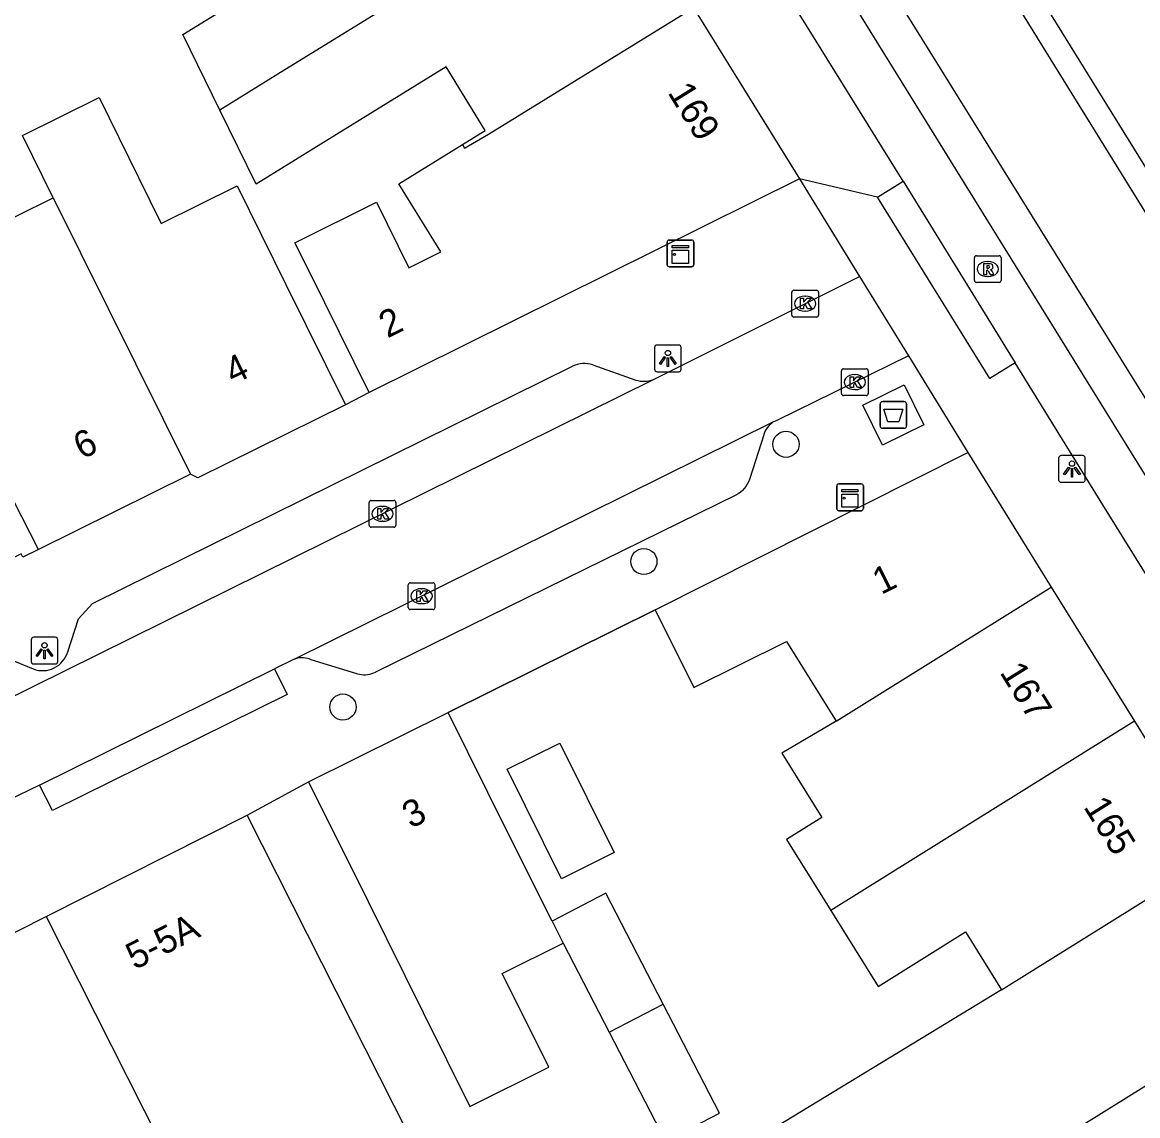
# Model space of a CAD drawing. Extents: x 159888 to 160757, y 384031 to 384746.
# Drawn here: x 160649.94 to 160691.65, y 384191.91 to 384232.8 of the extents above; entities that cross this region are included whole.
import ezdxf

# ---------------------------------------------------------------- set-up
doc = ezdxf.new("R2010")
doc.units = 0
for name, color, linetype in [('IMGEO_Afval_apart_plaats', 7, 'Continuous'), ('IMGEO_Boom', 7, 'Continuous'), ('IMGEO_Kast', 7, 'Continuous'), ('IMGEO_Kolk', 7, 'Continuous'), ('IMGEO_Lichtpunt', 7, 'Continuous'), ('IMGEO_Muur', 7, 'Continuous'), ('IMGEO_Pand', 7, 'Continuous'), ('IMGEO_Pand_nummerreeks', 7, 'Continuous'), ('IMGEO_Rijbaan_lokaal_gesloten', 7, 'Continuous'), ('IMGEO_Rijbaan_lokaal_open', 7, 'Continuous'), ('IMGEO_Rioolput', 7, 'Continuous'), ('IMGEO_Voetpad_gesloten', 7, 'Continuous'), ('IMGEO_Voetpad_open', 7, 'Continuous')]:
    doc.layers.add(name, color=color, linetype=linetype)

msp = doc.modelspace()

# ---------------------------------------------------------------- linework, layer by layer
at = {"layer": 'IMGEO_Afval_apart_plaats'}
for p, q in [((160682.013, 384217.714), (160682.013, 384218.514)), ((160682.013, 384218.514), (160682.013, 384217.714)), ((160682.113, 384218.614), (160682.903, 384218.614)), ((160682.903, 384218.614), (160682.113, 384218.614)), ((160683.003, 384218.514), (160683.003, 384217.714)), ((160683.003, 384217.714), (160683.003, 384218.514)), ((160682.903, 384217.614), (160682.113, 384217.614)), ((160682.113, 384217.614), (160682.903, 384217.614))]:
    msp.add_line(p, q, dxfattribs=at)
msp.add_lwpolyline([(160682.156, 384218.328), (160682.86, 384218.328), (160682.711, 384217.858), (160682.305, 384217.858), (160682.156, 384218.328)], dxfattribs=at)
for centre, start, end in [((160682.113, 384218.514), 90, 180), ((160682.113, 384218.514), 90, 180), ((160682.903, 384218.514), 0, 90), ((160682.903, 384218.514), 360, 90), ((160682.113, 384217.714), 180, 270), ((160682.113, 384217.714), 180, 270), ((160682.903, 384217.714), 270, 0), ((160682.903, 384217.714), 270, 0)]:
    msp.add_arc(centre, 0.1, start, end, dxfattribs=at)
at = {"layer": 'IMGEO_Boom'}
for centre in [(160678.495, 384217.017), (160673.18, 384212.633), (160661.928, 384207.19)]:
    msp.add_circle(centre, 0.489, dxfattribs=at)
at = {"layer": 'IMGEO_Kast'}
for p, q in [((160674.048, 384223.73), (160674.048, 384224.571)), ((160674.048, 384224.571), (160674.048, 384223.73)), ((160674.123, 384224.655), (160674.964, 384224.655)), ((160674.964, 384224.655), (160674.123, 384224.655)), ((160675.048, 384224.58), (160675.048, 384223.739)), ((160675.048, 384223.739), (160675.048, 384224.58)), ((160674.973, 384223.655), (160674.132, 384223.655)), ((160674.132, 384223.655), (160674.973, 384223.655)), ((160680.39, 384214.609), (160680.39, 384215.45)), ((160680.39, 384215.45), (160680.39, 384214.609)), ((160680.465, 384215.534), (160681.306, 384215.534)), ((160681.306, 384215.534), (160680.465, 384215.534)), ((160681.39, 384215.459), (160681.39, 384214.618)), ((160681.39, 384214.618), (160681.39, 384215.459)), ((160681.315, 384214.534), (160680.474, 384214.534)), ((160680.474, 384214.534), (160681.315, 384214.534))]:
    msp.add_line(p, q, dxfattribs=at)
for points in [[(160674.243, 384224.445), (160674.843, 384224.445), (160674.843, 384224.36), (160674.243, 384224.36), (160674.243, 384224.445)], [(160674.243, 384224.27), (160674.843, 384224.27), (160674.843, 384223.781), (160674.243, 384223.781), (160674.243, 384224.27)], [(160680.585, 384215.324), (160681.185, 384215.324), (160681.185, 384215.239), (160680.585, 384215.239), (160680.585, 384215.324)], [(160680.585, 384215.149), (160681.185, 384215.149), (160681.185, 384214.66), (160680.585, 384214.66), (160680.585, 384215.149)]]:
    msp.add_lwpolyline(points, dxfattribs=at)
for centre in [(160674.327, 384224.119), (160680.669, 384214.998)]:
    msp.add_circle(centre, 0.0377, dxfattribs=at)
for centre, start, end in [((160674.126, 384224.577), 92.4484, 184.2845), ((160674.126, 384224.577), 92.4484, 184.2845), ((160674.97, 384224.577), 2.4484, 94.2845), ((160674.97, 384224.577), 2.4484, 94.2845), ((160674.126, 384223.733), 182.4484, 274.2845), ((160674.126, 384223.733), 182.4484, 274.2845), ((160674.97, 384223.733), 272.4484, 4.2845), ((160674.97, 384223.733), 272.4484, 4.2845), ((160680.468, 384215.456), 92.4484, 184.2845), ((160680.468, 384215.456), 92.4484, 184.2845), ((160681.312, 384215.456), 2.4484, 94.2845), ((160681.312, 384215.456), 2.4484, 94.2845), ((160680.468, 384214.612), 182.4484, 274.2845), ((160680.468, 384214.612), 182.4484, 274.2845), ((160681.312, 384214.612), 272.4484, 4.2845), ((160681.312, 384214.612), 272.4484, 4.2845)]:
    msp.add_arc(centre, 0.0779, start, end, dxfattribs=at)
at = {"layer": 'IMGEO_Kolk'}
for p, q in [((160678.71, 384221.85), (160678.71, 384222.702)), ((160678.785, 384222.776), (160679.637, 384222.776)), ((160679.198, 384222.556), (160679.223, 384222.556)), ((160679.711, 384222.702), (160679.711, 384221.85)), ((160679.637, 384221.776), (160678.785, 384221.776)), ((160679.221, 384221.996), (160679.196, 384221.996)), ((160680.569, 384218.915), (160680.569, 384219.767)), ((160680.644, 384219.841), (160681.496, 384219.841)), ((160681.057, 384219.621), (160681.082, 384219.621)), ((160681.57, 384219.767), (160681.57, 384218.915)), ((160681.496, 384218.841), (160680.644, 384218.841)), ((160681.08, 384219.061), (160681.055, 384219.061)), ((160662.906, 384213.99), (160662.906, 384214.842)), ((160662.981, 384214.916), (160663.833, 384214.916)), ((160663.394, 384214.696), (160663.419, 384214.696)), ((160663.907, 384214.842), (160663.907, 384213.99)), ((160663.417, 384214.136), (160663.392, 384214.136)), ((160663.833, 384213.916), (160662.981, 384213.916)), ((160664.368, 384210.911), (160664.368, 384211.763)), ((160664.443, 384211.837), (160665.295, 384211.837)), ((160664.856, 384211.617), (160664.881, 384211.617)), ((160665.369, 384211.763), (160665.369, 384210.911)), ((160665.295, 384210.837), (160664.443, 384210.837)), ((160664.879, 384211.057), (160664.854, 384211.057))]:
    msp.add_line(p, q, dxfattribs=at)
for points in [[(160678.71, 384221.85), (160678.71, 384222.702)], [(160678.785, 384222.776), (160679.637, 384222.776)], [(160679.031, 384222.476), (160679.154, 384222.476), (160679.154, 384222.325), (160679.284, 384222.476), (160679.448, 384222.476), (160679.302, 384222.325), (160679.455, 384222.076), (160679.303, 384222.076), (160679.218, 384222.24), (160679.154, 384222.173), (160679.154, 384222.076), (160679.031, 384222.076), (160679.031, 384222.476)], [(160679.711, 384222.702), (160679.711, 384221.85)], [(160679.637, 384221.776), (160678.785, 384221.776)], [(160680.569, 384218.915), (160680.569, 384219.767)], [(160680.644, 384219.841), (160681.496, 384219.841)], [(160680.89, 384219.541), (160681.013, 384219.541), (160681.013, 384219.39), (160681.143, 384219.541), (160681.307, 384219.541), (160681.161, 384219.39), (160681.314, 384219.141), (160681.162, 384219.141), (160681.077, 384219.305), (160681.013, 384219.238), (160681.013, 384219.141), (160680.89, 384219.141), (160680.89, 384219.541)], [(160681.57, 384219.767), (160681.57, 384218.915)], [(160681.496, 384218.841), (160680.644, 384218.841)], [(160662.906, 384213.99), (160662.906, 384214.842)], [(160662.981, 384214.916), (160663.833, 384214.916)], [(160663.227, 384214.616), (160663.35, 384214.616), (160663.35, 384214.465), (160663.48, 384214.616), (160663.644, 384214.616), (160663.498, 384214.465), (160663.651, 384214.216), (160663.499, 384214.216), (160663.414, 384214.38), (160663.35, 384214.313), (160663.35, 384214.216), (160663.227, 384214.216), (160663.227, 384214.616)], [(160663.907, 384214.842), (160663.907, 384213.99)], [(160663.833, 384213.916), (160662.981, 384213.916)], [(160664.368, 384210.911), (160664.368, 384211.763)], [(160664.443, 384211.837), (160665.295, 384211.837)], [(160665.369, 384211.763), (160665.369, 384210.911)], [(160664.689, 384211.537), (160664.812, 384211.537), (160664.812, 384211.386), (160664.942, 384211.537), (160665.106, 384211.537), (160664.96, 384211.386), (160665.113, 384211.137), (160664.961, 384211.137), (160664.876, 384211.301), (160664.812, 384211.234), (160664.812, 384211.137), (160664.689, 384211.137), (160664.689, 384211.537)], [(160665.295, 384210.837), (160664.443, 384210.837)]]:
    msp.add_lwpolyline(points, dxfattribs=at)
for centre, start, end in [((160678.787, 384222.7), 91.552, 178.448), ((160678.787, 384222.7), 91.552, 178.448), ((160679.635, 384222.7), 1.552, 88.448), ((160679.635, 384222.7), 1.552, 88.448), ((160678.787, 384221.852), 181.552, 268.448), ((160678.787, 384221.852), 181.552, 268.448), ((160679.635, 384221.852), 271.552, 358.448), ((160679.635, 384221.852), 271.552, 358.448), ((160680.646, 384219.765), 91.552, 178.448), ((160680.646, 384219.765), 91.552, 178.448), ((160681.494, 384219.765), 1.552, 88.448), ((160681.494, 384219.765), 1.552, 88.448), ((160680.646, 384218.917), 181.552, 268.448), ((160680.646, 384218.917), 181.552, 268.448), ((160681.494, 384218.917), 271.552, 358.448), ((160681.494, 384218.917), 271.552, 358.448), ((160662.983, 384214.84), 91.552, 178.448), ((160662.983, 384214.84), 91.552, 178.448), ((160663.831, 384214.84), 1.552, 88.448), ((160663.831, 384214.84), 1.552, 88.448), ((160662.983, 384213.992), 181.552, 268.448), ((160662.983, 384213.992), 181.552, 268.448), ((160663.831, 384213.992), 271.552, 358.448), ((160663.831, 384213.992), 271.552, 358.448), ((160664.445, 384211.761), 91.552, 178.448), ((160664.445, 384211.761), 91.552, 178.448), ((160665.293, 384211.761), 1.552, 88.448), ((160665.293, 384211.761), 1.552, 88.448), ((160664.445, 384210.913), 181.552, 268.448), ((160664.445, 384210.913), 181.552, 268.448), ((160665.293, 384210.913), 271.552, 358.448), ((160665.293, 384210.913), 271.552, 358.448)]:
    msp.add_arc(centre, 0.0765, start, end, dxfattribs=at)
for centre, major_axis, ratio, start_param, end_param in [((160679.197, 384222.276), (-0.387, 0.002), 0.722429, 4.712389, 7.853982), ((160679.222, 384222.276), (-0.39, 0.002), 0.717154, 1.570796, 4.712389), ((160681.056, 384219.341), (-0.387, 0.002), 0.722429, 4.712389, 7.853982), ((160681.081, 384219.341), (-0.39, 0.002), 0.717154, 1.570796, 4.712389), ((160663.393, 384214.416), (-0.387, 0.002), 0.722429, 4.712389, 7.853982), ((160663.418, 384214.416), (-0.39, 0.002), 0.717154, 1.570796, 4.712389), ((160664.855, 384211.337), (-0.387, 0.002), 0.722429, 4.712389, 7.853982), ((160664.88, 384211.337), (-0.39, 0.002), 0.717154, 1.570796, 4.712389)]:
    msp.add_ellipse(centre, major_axis=major_axis, ratio=ratio, start_param=start_param, end_param=end_param, dxfattribs=at)
at = {"layer": 'IMGEO_Lichtpunt'}
for p, q in [((160673.579, 384220.632), (160673.579, 384219.825)), ((160673.579, 384220.632), (160673.579, 384219.825)), ((160674.481, 384220.727), (160673.673, 384220.727)), ((160674.481, 384220.727), (160673.673, 384220.727)), ((160674.575, 384219.825), (160674.575, 384220.632)), ((160674.575, 384219.825), (160674.575, 384220.632)), ((160673.673, 384219.731), (160674.481, 384219.731)), ((160673.673, 384219.731), (160674.481, 384219.731)), ((160688.69, 384216.498), (160688.69, 384215.691)), ((160688.69, 384216.498), (160688.69, 384215.691)), ((160689.592, 384216.593), (160688.784, 384216.593)), ((160689.592, 384216.593), (160688.784, 384216.593)), ((160689.686, 384215.691), (160689.686, 384216.498)), ((160689.686, 384215.691), (160689.686, 384216.498)), ((160688.784, 384215.597), (160689.592, 384215.597)), ((160688.784, 384215.597), (160689.592, 384215.597)), ((160650.269, 384209.705), (160650.269, 384208.898)), ((160650.269, 384209.705), (160650.269, 384208.898)), ((160651.171, 384209.8), (160650.363, 384209.8)), ((160651.171, 384209.8), (160650.363, 384209.8)), ((160651.265, 384208.898), (160651.265, 384209.705)), ((160651.265, 384208.898), (160651.265, 384209.705)), ((160650.363, 384208.804), (160651.171, 384208.804)), ((160650.363, 384208.804), (160651.171, 384208.804))]:
    msp.add_line(p, q, dxfattribs=at)
for points in [[(160673.953, 384220.296), (160673.992, 384220.268), (160673.804, 384220.006), (160673.766, 384220.033), (160673.953, 384220.296)], [(160674.055, 384220.248), (160674.102, 384220.248), (160674.102, 384219.926), (160674.055, 384219.926), (160674.055, 384220.248)], [(160674.165, 384220.268), (160674.203, 384220.295), (160674.39, 384220.033), (160674.351, 384220.005), (160674.165, 384220.268)], [(160689.064, 384216.162), (160689.103, 384216.134), (160688.915, 384215.872), (160688.877, 384215.899), (160689.064, 384216.162)], [(160689.166, 384216.114), (160689.213, 384216.114), (160689.213, 384215.792), (160689.166, 384215.792), (160689.166, 384216.114)], [(160689.276, 384216.134), (160689.314, 384216.161), (160689.501, 384215.899), (160689.462, 384215.871), (160689.276, 384216.134)], [(160650.643, 384209.369), (160650.682, 384209.341), (160650.494, 384209.079), (160650.456, 384209.106), (160650.643, 384209.369)], [(160650.745, 384209.321), (160650.792, 384209.321), (160650.792, 384208.999), (160650.745, 384208.999), (160650.745, 384209.321)], [(160650.855, 384209.341), (160650.893, 384209.368), (160651.08, 384209.106), (160651.041, 384209.078), (160650.855, 384209.341)]]:
    msp.add_lwpolyline(points, dxfattribs=at)
for centre in [(160674.078, 384220.43), (160689.189, 384216.296), (160650.768, 384209.503)]:
    msp.add_circle(centre, 0.0994, dxfattribs=at)
for centre, start, end in [((160673.673, 384220.632), 90, 180), ((160673.673, 384220.632), 90, 180), ((160674.481, 384220.632), 0, 90), ((160674.481, 384220.632), 0, 90), ((160673.673, 384219.825), 180, 270), ((160673.673, 384219.825), 180, 270), ((160674.481, 384219.825), 270, 0), ((160674.481, 384219.825), 270, 360), ((160688.784, 384216.498), 90, 180), ((160688.784, 384216.498), 90, 180), ((160689.592, 384216.498), 0, 90), ((160689.592, 384216.498), 0, 90), ((160688.784, 384215.691), 180, 270), ((160688.784, 384215.691), 180, 270), ((160689.592, 384215.691), 270, 0), ((160689.592, 384215.691), 270, 360), ((160650.363, 384209.705), 90, 180), ((160650.363, 384209.705), 90, 180), ((160651.171, 384209.705), 0, 90), ((160651.171, 384209.705), 0, 90), ((160650.363, 384208.898), 180, 270), ((160650.363, 384208.898), 180, 270), ((160651.171, 384208.898), 270, 0), ((160651.171, 384208.898), 270, 360)]:
    msp.add_arc(centre, 0.0946, start, end, dxfattribs=at)
at = {"layer": 'IMGEO_Muur'}
msp.add_lwpolyline([(160673.598, 384210.83), (160665.86, 384206.987)], dxfattribs=at)
at = {"layer": 'IMGEO_Pand'}
for points in [[(160657.328, 384229.515), (160655.945, 384232.335), (160657.853, 384233.512), (160662.545, 384236.406), (160660.934, 384239.017)], [(160671.847, 384238.47), (160659.494, 384230.851), (160657.328, 384229.515)], [(160666.399, 384228.221), (160666.475, 384228.095), (160667.372, 384228.613), (160675.03, 384233.336)], [(160675.03, 384233.336), (160678.996, 384226.937)], [(160666.399, 384228.221), (160667.25, 384228.746), (160665.782, 384231.126), (160661.104, 384228.241), (160658.685, 384226.749), (160657.328, 384229.515)], [(160651.091, 384226.236), (160649.946, 384228.562), (160652.809, 384229.978), (160654.283, 384226.998), (160655.136, 384225.274), (160657.971, 384226.676), (160659.79, 384222.989), (160662.02, 384218.494)], [(160662.908, 384218.955), (160660.686, 384223.434), (160660.129, 384224.555), (160663.179, 384226.068), (160664.394, 384223.618), (160665.582, 384224.207), (160664.014, 384226.75), (160666.399, 384228.221)], [(160678.996, 384226.937), (160662.908, 384218.955)], [(160645.281, 384223.362), (160648.366, 384224.888), (160651.091, 384226.236)], [(160651.091, 384226.236), (160656.229, 384215.896)], [(160650.541, 384213.08), (160645.281, 384223.362)], [(160662.02, 384218.494), (160656.495, 384215.761), (160656.229, 384215.896)], [(160673.598, 384210.83), (160685.288, 384216.712)], [(160685.288, 384216.712), (160688.415, 384211.673)], [(160656.229, 384215.896), (160650.541, 384213.08)], [(160650.541, 384213.08), (160649.956, 384212.791), (160649.889, 384212.925), (160648.732, 384212.352), (160648.556, 384211.832), (160644.57, 384209.86)], [(160680.37, 384206.667), (160688.415, 384211.673)], [(160688.415, 384211.673), (160691.525, 384206.661)], [(160673.598, 384210.83), (160675.044, 384207.922), (160678.514, 384209.648), (160680.37, 384206.667)], [(160660.644, 384204.395), (160665.86, 384206.987)], [(160669.751, 384199.187), (160668.085, 384202.51), (160665.86, 384206.987)], [(160680.37, 384206.667), (160678.336, 384205.463), (160679.83, 384203.065), (160678.511, 384202.244), (160680.165, 384199.587)], [(160691.525, 384206.661), (160680.165, 384199.587)], [(160691.525, 384206.661), (160694.635, 384201.648)], [(160670.096, 384200.773), (160668.064, 384204.862), (160670.042, 384205.845), (160672.074, 384201.756), (160670.096, 384200.773)], [(160660.644, 384204.395), (160662.869, 384199.918), (160664.932, 384195.766), (160666.678, 384192.252), (160669.631, 384193.719), (160667.885, 384197.233), (160670.163, 384198.364)], [(160650.827, 384199.354), (160658.343, 384203.154)], [(160660.564, 384181.252), (160667.614, 384184.816), (160660.599, 384198.692), (160658.343, 384203.154)], [(160686.554, 384196.619), (160694.635, 384201.648)], [(160673.903, 384196.08), (160671.756, 384200.226), (160669.751, 384199.187)], [(160680.165, 384199.587), (160681.936, 384196.743), (160685.208, 384198.78), (160686.554, 384196.619)], [(160645.288, 384196.144), (160646.908, 384196.934), (160646.735, 384197.286), (160650.827, 384199.354)], [(160650.827, 384199.354), (160655.718, 384189.681)], [(160669.751, 384199.187), (160670.163, 384198.364)], [(160670.163, 384198.364), (160671.887, 384195.032)], [(160686.554, 384196.619), (160674.878, 384189.514), (160677.899, 384184.55), (160682.168, 384187.071)], [(160697.746, 384196.634), (160686.466, 384189.61), (160682.168, 384187.071)], [(160671.887, 384195.032), (160673.903, 384196.08)], [(160671.887, 384195.032), (160673.994, 384190.964), (160676.011, 384192.009), (160673.903, 384196.08)]]:
    msp.add_lwpolyline(points, dxfattribs=at)
at = {"layer": 'IMGEO_Rijbaan_lokaal_gesloten'}
for points in [[(160632.074, 384323.722), (160677.924, 384250), (160717.593, 384185.942), (160721.789, 384179.196), (160722.103, 384178.75)], [(160721.392, 384178.231), (160720.54, 384179.603), (160716.199, 384186.525), (160676.893, 384250), (160631.369, 384323.299)], [(160716.812, 384178.507), (160712.066, 384186.351), (160658.156, 384273.096), (160628.254, 384321.427)], [(160725.705, 384157.813), (160717.699, 384173.243), (160713.185, 384181.538), (160666.822, 384256.425), (160627.201, 384320.153), (160626.898, 384320.642)]]:
    msp.add_lwpolyline(points, dxfattribs=at)
at = {"layer": 'IMGEO_Rijbaan_lokaal_open'}
for points in [[(160673.544, 384219.435), (160681.241, 384223.295)], [(160681.241, 384223.295), (160683.08, 384220.328)], [(160683.08, 384220.328), (160678.178, 384217.924), (160678.008, 384217.84)], [(160647.891, 384206.746), (160673.544, 384219.435)], [(160678.008, 384217.84), (160660.093, 384208.974)], [(160660.093, 384208.974), (160660.082, 384208.969), (160659.372, 384208.618)], [(160650.586, 384204.276), (160659.372, 384208.618)], [(160650.586, 384204.276), (160649.402, 384203.691)]]:
    msp.add_lwpolyline(points, dxfattribs=at)
at = {"layer": 'IMGEO_Rioolput'}
for p, q in [((160685.539, 384223.142), (160685.539, 384223.994)), ((160685.614, 384224.068), (160686.466, 384224.068)), ((160686.027, 384223.848), (160686.052, 384223.848)), ((160686.54, 384223.994), (160686.54, 384223.142)), ((160686.05, 384223.288), (160686.025, 384223.288)), ((160686.466, 384223.068), (160685.614, 384223.068))]:
    msp.add_line(p, q, dxfattribs=at)
for points in [[(160685.539, 384223.142), (160685.539, 384223.994)], [(160685.614, 384224.068), (160686.466, 384224.068)], [(160686.128, 384223.766), (160685.876, 384223.768), (160685.876, 384223.368)], [(160686.54, 384223.994), (160686.54, 384223.142)], [(160685.876, 384223.368), (160686, 384223.368), (160686, 384223.53), (160686.011, 384223.53)], [(160686.054, 384223.687), (160686, 384223.687), (160686, 384223.606)], [(160686, 384223.606), (160686.052, 384223.606)], [(160686.058, 384223.501), (160686.129, 384223.368), (160686.269, 384223.368), (160686.204, 384223.494)], [(160686.466, 384223.068), (160685.614, 384223.068)]]:
    msp.add_lwpolyline(points, dxfattribs=at)
for centre, radius, start, end in [((160685.616, 384223.992), 0.0765, 91.552, 178.448), ((160685.616, 384223.992), 0.0765, 91.552, 178.448), ((160686.127, 384223.656), 0.109, 350.3612, 89.416), ((160686.464, 384223.992), 0.0765, 1.552, 88.448), ((160686.464, 384223.992), 0.0765, 1.552, 88.448), ((160686.01, 384223.477), 0.0533, 26.0293, 88.6989), ((160686.036, 384223.795), 0.19, 274.7715, 282.9687), ((160686.06, 384223.591), 0.0964, 77.0061, 93.1865), ((160686.074, 384223.648), 0.0378, 276.6634, 79.6772), ((160686.125, 384223.656), 0.112, 277.5842, 350.9817), ((160686.109, 384223.441), 0.108, 29.5134, 73.7905), ((160685.616, 384223.144), 0.0765, 181.552, 268.448), ((160685.616, 384223.144), 0.0765, 181.552, 268.448), ((160686.464, 384223.144), 0.0765, 271.552, 358.448), ((160686.464, 384223.144), 0.0765, 271.552, 358.448)]:
    msp.add_arc(centre, radius, start, end, dxfattribs=at)
for centre, major_axis, ratio, start_param, end_param in [((160686.026, 384223.568), (-0.387, 0.002), 0.722429, 4.712389, 7.853982), ((160686.051, 384223.568), (-0.39, 0.002), 0.717154, 1.570796, 4.712389)]:
    msp.add_ellipse(centre, major_axis=major_axis, ratio=ratio, start_param=start_param, end_param=end_param, dxfattribs=at)
at = {"layer": 'IMGEO_Voetpad_gesloten'}
msp.add_lwpolyline([(160681.366, 384218.48), (160682.915, 384219.242), (160683.65, 384217.749), (160682.101, 384216.987), (160681.366, 384218.48)], dxfattribs=at)
at = {"layer": 'IMGEO_Voetpad_open'}
for points in [[(160682.874, 384226.85), (160668.501, 384250), (160625.204, 384319.595), (160623.028, 384323.095)], [(160681.922, 384226.262), (160678.996, 384226.937)], [(160678.996, 384226.937), (160681.241, 384223.295)], [(160681.922, 384226.262), (160682.874, 384226.85)], [(160682.874, 384226.85), (160687.066, 384220.06)], [(160687.066, 384220.06), (160686.114, 384219.472), (160681.922, 384226.262)], [(160671.272, 384219.988), (160672.875, 384219.417)], [(160683.08, 384220.328), (160685.288, 384216.712)], [(160703.28, 384193.928), (160690.34, 384214.758), (160687.066, 384220.06)], [(160651.636, 384209.256), (160652.043, 384210.484), (160652.563, 384211.061), (160670.516, 384219.937)], [(160662.908, 384218.955), (160662.02, 384218.494)], [(160678.008, 384217.84), (160677.948, 384217.797), (160677.893, 384217.75), (160677.843, 384217.698), (160677.797, 384217.642), (160677.756, 384217.582), (160677.721, 384217.518), (160677.692, 384217.452), (160677.669, 384217.383), (160677.664, 384217.366), (160677.141, 384215.732), (160677.13, 384215.7), (160677.091, 384215.609), (160677.045, 384215.522), (160676.991, 384215.439), (160676.93, 384215.362), (160676.862, 384215.29), (160676.788, 384215.225), (160676.708, 384215.166), (160676.624, 384215.115), (160663.143, 384208.496), (160663.131, 384208.489), (160663.064, 384208.456), (160662.995, 384208.429), (160662.923, 384208.408), (160662.85, 384208.393), (160662.775, 384208.386), (160662.7, 384208.384), (160662.626, 384208.39), (160662.552, 384208.402), (160662.479, 384208.421), (160662.409, 384208.446), (160660.736, 384208.961), (160660.668, 384208.988), (160660.597, 384209.009), (160660.526, 384209.023), (160660.453, 384209.031), (160660.379, 384209.033), (160660.306, 384209.028), (160660.234, 384209.016), (160660.163, 384208.998), (160660.093, 384208.974)], [(160665.86, 384206.987), (160673.598, 384210.83)], [(160649.43, 384208.994), (160650.342, 384208.615)], [(160659.372, 384208.618), (160659.847, 384207.66), (160651.061, 384203.317), (160650.586, 384204.276)], [(160658.343, 384203.154), (160660.644, 384204.395)]]:
    msp.add_lwpolyline(points, dxfattribs=at)
for centre, radius, start, end in [((160670.959, 384218.999), 1.037, 72.4336, 115.2851), ((160673.182, 384220.455), 1.082, 253.5337, 289.5487), ((160650.692, 384209.535), 0.984, 249.1735, 343.5308)]:
    msp.add_arc(centre, radius, start, end, dxfattribs=at)

# ---------------------------------------------------------------- texts
at = {"layer": 'IMGEO_Pand_nummerreeks'}
for s, rotation, p in [('169', 301.79, (160674.051, 384230.17)), ('2', 26.3881, (160663.593, 384220.97)), ('4', 26.3003, (160657.827, 384219.233)), ('6', 26.3003, (160652.169, 384216.436)), ('1', 26.4535, (160682.052, 384211.377)), ('167', 301.9078, (160686.466, 384208.488)), ('3', 26.4248, (160664.465, 384202.631)), ('165', 301.9078, (160689.597, 384203.459)), ('5-5A', 26.9802, (160654.142, 384197.35))]:
    msp.add_text(s, height=1, rotation=rotation, dxfattribs=at).set_placement(p)

doc.saveas('drawing.dxf')
